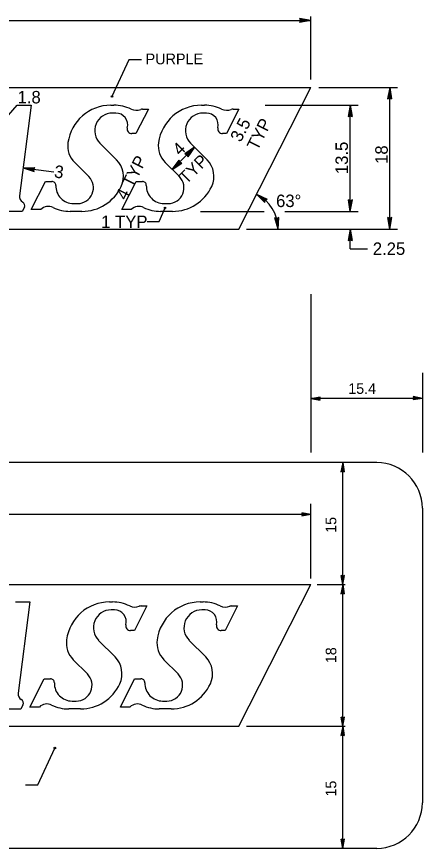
# Model space of a CAD drawing. Extents: x 10268197 to 10269179, y 2141503 to 2142677.
# Drawn here: x 10268707.3 to 10268734, y 2142212.3 to 2142267 of the extents above; entities that cross this region are included whole.
import ezdxf

# ---------------------------------------------------------------- set-up
doc = ezdxf.new("R2010")
doc.units = 0
for name, color, linetype in [('1', 7, 'Continuous'), ('2', 7, 'Continuous'), ('21', 7, 'Continuous'), ('52', 7, 'Continuous'), ('SOILS_SP83_SHP', 7, 'Continuous')]:
    doc.layers.add(name, color=color, linetype=linetype)

msp = doc.modelspace()

# ---------------------------------------------------------------- linework, layer by layer
at = {"layer": '1'}
for p, q in [((10268726.659, 2142262.902), (10268726.659, 2142267.042)), ((10268704.204, 2142266.783), (10268726.659, 2142266.783)), ((10268714.696, 2142264.199), (10268713.581, 2142261.792)), ((10268715.518, 2142264.199), (10268714.696, 2142264.199)), ((10268727.176, 2142262.385), (10268732.351, 2142262.385)), ((10268731.833, 2142253.071), (10268731.833, 2142262.385)), ((10268723.657, 2142261.22), (10268729.764, 2142261.22)), ((10268729.246, 2142254.235), (10268729.246, 2142261.22)), ((10268717.551, 2142256.985), (10268719.015, 2142258.448)), ((10268707.744, 2142257.097), (10268709.761, 2142256.835)), ((10268716.692, 2142253.575), (10268717.072, 2142254.463)), ((10268719.401, 2142254.235), (10268723.596, 2142254.235)), ((10268724.948, 2142254.235), (10268729.764, 2142254.235)), ((10268715.888, 2142253.575), (10268716.692, 2142253.575)), ((10268722.431, 2142253.071), (10268732.351, 2142253.071)), ((10268729.246, 2142251.778), (10268729.246, 2142253.071)), ((10268729.246, 2142251.778), (10268730.371, 2142251.778)), ((10268726.659, 2142248.802), (10268726.659, 2142238.369)), ((10268733.979, 2142243.611), (10268733.979, 2142238.369)), ((10268733.421, 2142241.949), (10268733.373, 2142241.843)), ((10268733.979, 2142241.939), (10268733.373, 2142241.843)), ((10268733.979, 2142241.939), (10268733.377, 2142242.056)), ((10268733.377, 2142242.056), (10268733.421, 2142241.949)), ((10268733.979, 2142241.939), (10268733.399, 2142241.899)), ((10268733.979, 2142241.939), (10268733.401, 2142242)), ((10268728.747, 2142237.716), (10268728.631, 2142237.115)), ((10268728.747, 2142237.716), (10268728.687, 2142237.138)), ((10268728.747, 2142229.69), (10268728.747, 2142237.716)), ((10268728.747, 2142237.716), (10268728.844, 2142237.111)), ((10268728.747, 2142237.716), (10268728.788, 2142237.137)), ((10268728.631, 2142237.115), (10268728.738, 2142237.159)), ((10268728.738, 2142237.159), (10268728.844, 2142237.111)), ((10268726.659, 2142230.104), (10268726.659, 2142234.996)), ((10268726.102, 2142234.302), (10268726.053, 2142234.196)), ((10268726.659, 2142234.292), (10268726.053, 2142234.196)), ((10268726.659, 2142234.292), (10268726.057, 2142234.409)), ((10268726.057, 2142234.409), (10268726.102, 2142234.302)), ((10268726.659, 2142234.292), (10268726.079, 2142234.252)), ((10268726.659, 2142234.292), (10268726.081, 2142234.353)), ((10268728.747, 2142229.69), (10268728.652, 2142230.295)), ((10268728.757, 2142230.247), (10268728.652, 2142230.295)), ((10268728.747, 2142229.69), (10268728.707, 2142230.27)), ((10268728.747, 2142229.69), (10268728.864, 2142230.292)), ((10268728.747, 2142229.69), (10268728.808, 2142230.269)), ((10268728.864, 2142230.292), (10268728.757, 2142230.247)), ((10268727.073, 2142229.69), (10268728.904, 2142229.69)), ((10268728.747, 2142229.69), (10268728.631, 2142229.088)), ((10268728.747, 2142229.69), (10268728.687, 2142229.111)), ((10268728.747, 2142220.374), (10268728.747, 2142229.69)), ((10268728.747, 2142229.69), (10268728.844, 2142229.084)), ((10268728.747, 2142229.69), (10268728.788, 2142229.11)), ((10268728.631, 2142229.088), (10268728.738, 2142229.133)), ((10268728.738, 2142229.133), (10268728.844, 2142229.084)), ((10268728.747, 2142220.374), (10268728.652, 2142220.979)), ((10268728.757, 2142220.931), (10268728.652, 2142220.979)), ((10268728.747, 2142220.374), (10268728.707, 2142220.954)), ((10268728.747, 2142220.374), (10268728.864, 2142220.976)), ((10268728.747, 2142220.374), (10268728.808, 2142220.953)), ((10268728.864, 2142220.976), (10268728.757, 2142220.931)), ((10268722.43, 2142220.374), (10268728.904, 2142220.374)), ((10268728.747, 2142220.374), (10268728.631, 2142219.772)), ((10268728.747, 2142220.374), (10268728.687, 2142219.795)), ((10268728.747, 2142212.347), (10268728.747, 2142220.374)), ((10268728.747, 2142220.374), (10268728.844, 2142219.768)), ((10268728.747, 2142220.374), (10268728.788, 2142219.794)), ((10268728.631, 2142219.772), (10268728.738, 2142219.816)), ((10268728.738, 2142219.816), (10268728.844, 2142219.768)), ((10268708.719, 2142216.536), (10268709.835, 2142218.944)), ((10268707.897, 2142216.536), (10268708.719, 2142216.536)), ((10268728.747, 2142212.347), (10268728.652, 2142212.953)), ((10268728.757, 2142212.905), (10268728.652, 2142212.953)), ((10268728.747, 2142212.347), (10268728.707, 2142212.927)), ((10268728.747, 2142212.347), (10268728.864, 2142212.949)), ((10268728.747, 2142212.347), (10268728.808, 2142212.926)), ((10268728.864, 2142212.949), (10268728.757, 2142212.905))]:
    msp.add_line(p, q, dxfattribs=at)
for centre, radius in [((10268713.581, 2142261.791), 0.0517), ((10268717.072, 2142254.462), 0.0517), ((10268709.835, 2142218.944), 0.0518)]:
    msp.add_circle(centre, radius, dxfattribs=at)
msp.add_arc((10268721.913, 2142253.07), 2.587, 0, 63.0012, dxfattribs=at)
at = {"layer": '2'}
for p, q in [((10268733.979, 2142241.939), (10268726.659, 2142241.939)), ((10268730.979, 2142237.716), (10268669.979, 2142237.716)), ((10268733.979, 2142234.716), (10268733.979, 2142215.347)), ((10268726.659, 2142234.292), (10268674.298, 2142234.292)), ((10268697.136, 2142229.69), (10268726.659, 2142229.69)), ((10268721.913, 2142220.374), (10268726.659, 2142229.69)), ((10268707.256, 2142228.551), (10268708.188, 2142228.551)), ((10268708.188, 2142228.551), (10268707.413, 2142222.551)), ((10268713.423, 2142228.551), (10268713.619, 2142228.551)), ((10268713.751, 2142228.03), (10268713.529, 2142228.03)), ((10268715.885, 2142228.291), (10268715.063, 2142226.665)), ((10268715.497, 2142228.291), (10268715.885, 2142228.291)), ((10268719.375, 2142228.551), (10268719.571, 2142228.551)), ((10268719.702, 2142228.03), (10268719.48, 2142228.03)), ((10268721.837, 2142228.291), (10268721.014, 2142226.665)), ((10268721.449, 2142228.291), (10268721.837, 2142228.291)), ((10268715.063, 2142226.665), (10268714.804, 2142226.665)), ((10268721.014, 2142226.665), (10268720.756, 2142226.665)), ((10268712.705, 2142226.027), (10268713.79, 2142224.935)), ((10268718.657, 2142226.027), (10268719.742, 2142224.935)), ((10268711.974, 2142223.814), (10268711.043, 2142224.752)), ((10268717.926, 2142223.814), (10268716.994, 2142224.752)), ((10268708.185, 2142221.643), (10268709.124, 2142223.502)), ((10268709.124, 2142223.502), (10268709.54, 2142223.502)), ((10268714.136, 2142221.643), (10268715.076, 2142223.502)), ((10268715.076, 2142223.502), (10268715.492, 2142223.502)), ((10268710.963, 2142222.034), (10268711.243, 2142222.034)), ((10268716.915, 2142222.034), (10268717.194, 2142222.034)), ((10268707.601, 2142221.512), (10268705.014, 2142221.512)), ((10268707.737, 2142221.781), (10268707.601, 2142221.512)), ((10268708.813, 2142221.643), (10268708.185, 2142221.643)), ((10268711.52, 2142221.513), (10268710.742, 2142221.513)), ((10268714.765, 2142221.643), (10268714.136, 2142221.643)), ((10268717.472, 2142221.513), (10268716.693, 2142221.513)), ((10268696.271, 2142220.374), (10268721.913, 2142220.374)), ((10268730.979, 2142212.347), (10268669.979, 2142212.347))]:
    msp.add_line(p, q, dxfattribs=at)
for centre, start, end in [((10268730.979, 2142234.716), 0, 90), ((10268730.979, 2142215.347), 270, 0)]:
    msp.add_arc(centre, 3, start, end, dxfattribs=at)
for centre, major_axis, start_param, end_param in [((10268713.423, 2142225.684), (0, 2.868), 0, 1.436562), ((10268713.529, 2142226.857), (0, -1.173), 3.141593, 5.497787), ((10268713.619, 2142225.945), (0, 2.607), 5.830963, 6.283185), ((10268713.751, 2142227.248), (0, -0.782), 1.321066, 3.141593), ((10268715.089, 2142228.993), (0, 0.782), 2.68937, 3.526171), ((10268715.497, 2142227.978), (0, 0.313), 0, 0.384579), ((10268719.375, 2142225.684), (0, 2.868), 0, 1.436562), ((10268719.48, 2142226.857), (0, -1.173), 3.141593, 5.497787), ((10268719.571, 2142225.945), (0, 2.607), 5.830963, 6.283185), ((10268719.702, 2142227.248), (0, -0.782), 1.321066, 3.141593), ((10268721.041, 2142228.993), (0, 0.782), 2.68937, 3.526171), ((10268721.449, 2142227.978), (0, 0.313), 0, 0.384579), ((10268714.804, 2142226.978), (0, -0.313), 4.462658, 6.283185), ((10268720.756, 2142226.978), (0, -0.313), 4.462658, 6.283185), ((10268712.141, 2142225.858), (0, 1.564), 1.436562, 2.356194), ((10268718.092, 2142225.858), (0, 1.564), 1.436562, 2.356194), ((10268712.692, 2142223.829), (0, -1.564), 1.133591, 2.356194), ((10268718.644, 2142223.829), (0, -1.564), 1.133591, 2.356194), ((10268711.242, 2142223.077), (0, -1.043), 0, 2.356194), ((10268717.194, 2142223.077), (0, -1.043), 0, 2.356194), ((10268709.54, 2142223.241), (0, 0.261), 4.689114, 6.283185), ((10268710.963, 2142223.207), (0, 1.173), 1.547521, 3.141593), ((10268711.52, 2142224.381), (0, -2.868), 0, 1.133591), ((10268715.492, 2142223.241), (0, 0.261), 4.689114, 6.283185), ((10268716.915, 2142223.207), (0, 1.173), 1.547521, 3.141593), ((10268717.472, 2142224.381), (0, -2.868), 0, 1.133591), ((10268707.824, 2142222.498), (0, 0.417), 1.441439, 2.650585), ((10268707.507, 2142221.9), (0, 0.261), 4.240773, 5.792177), ((10268709.309, 2142221.111), (0, -0.73), 2.69443, 3.895387), ((10268710.741, 2142224.12), (0, -2.607), 5.836023, 6.283185), ((10268715.261, 2142221.111), (0, -0.73), 2.69443, 3.895387), ((10268716.693, 2142224.12), (0, -2.607), 5.836023, 6.283185)]:
    msp.add_ellipse(centre, major_axis=major_axis, ratio=0.992614, start_param=start_param, end_param=end_param, dxfattribs=at)
at = {"layer": '21'}
for p, q in [((10268726.659, 2142241.939), (10268727.264, 2142242.035)), ((10268726.659, 2142241.939), (10268727.239, 2142241.98)), ((10268726.659, 2142241.939), (10268727.261, 2142241.822)), ((10268726.659, 2142241.939), (10268727.237, 2142241.879)), ((10268727.216, 2142241.93), (10268727.264, 2142242.035)), ((10268727.261, 2142241.822), (10268727.216, 2142241.93))]:
    msp.add_line(p, q, dxfattribs=at)
at = {"layer": '52'}
for p, q in [((10268726.659, 2142266.783), (10268725.907, 2142266.929)), ((10268725.907, 2142266.929), (10268725.962, 2142266.795)), ((10268726.659, 2142266.783), (10268725.936, 2142266.859)), ((10268725.962, 2142266.795), (10268725.903, 2142266.663)), ((10268726.659, 2142266.783), (10268725.903, 2142266.663)), ((10268726.659, 2142266.783), (10268725.935, 2142266.732)), ((10268731.833, 2142262.385), (10268731.687, 2142261.633)), ((10268731.833, 2142262.385), (10268731.758, 2142261.662)), ((10268731.833, 2142262.385), (10268731.953, 2142261.628)), ((10268731.833, 2142262.385), (10268731.884, 2142261.66)), ((10268731.687, 2142261.633), (10268731.821, 2142261.688)), ((10268731.821, 2142261.688), (10268731.953, 2142261.628)), ((10268729.246, 2142261.22), (10268729.1, 2142260.469)), ((10268729.246, 2142261.22), (10268729.171, 2142260.498)), ((10268729.246, 2142261.22), (10268729.366, 2142260.464)), ((10268729.246, 2142261.22), (10268729.297, 2142260.496)), ((10268729.1, 2142260.469), (10268729.234, 2142260.525)), ((10268729.234, 2142260.525), (10268729.366, 2142260.464)), ((10268719.015, 2142258.448), (10268718.38, 2142258.02)), ((10268719.015, 2142258.448), (10268718.45, 2142257.991)), ((10268719.015, 2142258.448), (10268718.538, 2142257.9)), ((10268719.015, 2142258.448), (10268718.565, 2142257.828)), ((10268717.551, 2142256.985), (10268718.001, 2142257.604)), ((10268718.052, 2142257.469), (10268718.001, 2142257.604)), ((10268718.38, 2142258.02), (10268718.514, 2142257.964)), ((10268718.514, 2142257.964), (10268718.565, 2142257.828)), ((10268707.744, 2142257.097), (10268708.51, 2142257.119)), ((10268707.744, 2142257.097), (10268708.47, 2142256.855)), ((10268707.744, 2142257.097), (10268708.451, 2142256.929)), ((10268707.744, 2142257.097), (10268708.469, 2142257.054)), ((10268708.433, 2142256.996), (10268708.51, 2142257.119)), ((10268717.551, 2142256.985), (10268718.028, 2142257.532)), ((10268717.551, 2142256.985), (10268718.116, 2142257.442)), ((10268717.551, 2142256.985), (10268718.186, 2142257.413)), ((10268718.186, 2142257.413), (10268718.052, 2142257.469)), ((10268708.47, 2142256.855), (10268708.433, 2142256.996)), ((10268723.088, 2142255.376), (10268723.777, 2142255.04)), ((10268723.088, 2142255.376), (10268723.62, 2142254.825)), ((10268723.088, 2142255.376), (10268723.637, 2142254.9)), ((10268723.088, 2142255.376), (10268723.711, 2142255.002)), ((10268723.62, 2142254.825), (10268723.651, 2142254.968)), ((10268723.651, 2142254.968), (10268723.777, 2142255.04)), ((10268729.246, 2142254.235), (10268729.126, 2142254.991)), ((10268729.258, 2142254.931), (10268729.126, 2142254.991)), ((10268729.246, 2142254.235), (10268729.195, 2142254.959)), ((10268729.246, 2142254.235), (10268729.392, 2142254.987)), ((10268729.246, 2142254.235), (10268729.321, 2142254.959)), ((10268729.392, 2142254.987), (10268729.258, 2142254.931)), ((10268724.5, 2142253.071), (10268724.276, 2142253.803)), ((10268724.416, 2142253.763), (10268724.276, 2142253.803)), ((10268724.5, 2142253.071), (10268724.35, 2142253.782)), ((10268724.54, 2142253.836), (10268724.416, 2142253.763)), ((10268724.5, 2142253.071), (10268724.476, 2142253.798)), ((10268724.5, 2142253.071), (10268724.54, 2142253.836)), ((10268731.833, 2142253.071), (10268731.713, 2142253.828)), ((10268731.845, 2142253.768), (10268731.713, 2142253.828)), ((10268731.833, 2142253.071), (10268731.783, 2142253.795)), ((10268731.833, 2142253.071), (10268731.979, 2142253.823)), ((10268731.833, 2142253.071), (10268731.908, 2142253.794)), ((10268731.979, 2142253.823), (10268731.845, 2142253.768)), ((10268729.246, 2142253.071), (10268729.1, 2142252.319)), ((10268729.246, 2142253.071), (10268729.171, 2142252.348)), ((10268729.246, 2142253.071), (10268729.366, 2142252.315)), ((10268729.246, 2142253.071), (10268729.297, 2142252.347)), ((10268729.1, 2142252.319), (10268729.234, 2142252.375)), ((10268729.234, 2142252.375), (10268729.366, 2142252.315))]:
    msp.add_line(p, q, dxfattribs=at)
at = {"layer": 'SOILS_SP83_SHP'}
for p, q in [((10268697.142, 2142262.385), (10268726.659, 2142262.385)), ((10268721.913, 2142253.071), (10268726.659, 2142262.385)), ((10268702.066, 2142255.144), (10268707.349, 2142261.22)), ((10268707.349, 2142261.22), (10268708.281, 2142261.22)), ((10268708.281, 2142261.22), (10268707.506, 2142255.266)), ((10268713.514, 2142261.22), (10268713.711, 2142261.22)), ((10268715.976, 2142260.961), (10268715.153, 2142259.348)), ((10268715.588, 2142260.961), (10268715.976, 2142260.961)), ((10268719.465, 2142261.22), (10268719.661, 2142261.22)), ((10268721.926, 2142260.961), (10268721.104, 2142259.348)), ((10268721.538, 2142260.961), (10268721.926, 2142260.961)), ((10268713.842, 2142260.703), (10268713.62, 2142260.703)), ((10268719.793, 2142260.703), (10268719.571, 2142260.703)), ((10268715.153, 2142259.348), (10268714.895, 2142259.348)), ((10268721.104, 2142259.348), (10268720.845, 2142259.348)), ((10268712.797, 2142258.716), (10268713.881, 2142257.631)), ((10268718.747, 2142258.716), (10268719.832, 2142257.631)), ((10268712.066, 2142256.519), (10268711.135, 2142257.45)), ((10268718.016, 2142256.519), (10268717.086, 2142257.45)), ((10268708.277, 2142254.365), (10268709.216, 2142256.209)), ((10268709.216, 2142256.209), (10268709.632, 2142256.209)), ((10268714.227, 2142254.365), (10268715.167, 2142256.209)), ((10268715.167, 2142256.209), (10268715.583, 2142256.209)), ((10268707.83, 2142254.502), (10268707.694, 2142254.235)), ((10268708.906, 2142254.365), (10268708.277, 2142254.365)), ((10268711.054, 2142254.752), (10268711.334, 2142254.752)), ((10268714.856, 2142254.365), (10268714.227, 2142254.365)), ((10268717.005, 2142254.752), (10268717.284, 2142254.752)), ((10268707.694, 2142254.235), (10268705.107, 2142254.235)), ((10268711.612, 2142254.235), (10268710.834, 2142254.235)), ((10268717.563, 2142254.235), (10268716.784, 2142254.235)), ((10268696.456, 2142253.071), (10268721.913, 2142253.071))]:
    msp.add_line(p, q, dxfattribs=at)
for centre, radius, start, end in [((10268713.514, 2142258.374), 2.846, 90, 172.3089), ((10268713.71, 2142258.633), 2.587, 64.0896, 90), ((10268715.18, 2142261.658), 0.776, 244.0896, 292.0347), ((10268715.588, 2142260.651), 0.31, 90, 112.0347), ((10268719.465, 2142258.374), 2.846, 90, 172.3089), ((10268719.661, 2142258.633), 2.587, 64.0896, 90), ((10268721.131, 2142261.658), 0.776, 244.0896, 292.0347), ((10268721.538, 2142260.651), 0.31, 90, 112.0347), ((10268713.62, 2142259.538), 1.164, 90, 225), ((10268713.842, 2142259.926), 0.776, 345.6915, 90), ((10268719.57, 2142259.538), 1.164, 90, 225), ((10268719.792, 2142259.926), 0.776, 345.6915, 90), ((10268714.895, 2142259.658), 0.31, 165.6915, 270), ((10268720.845, 2142259.658), 0.31, 165.6915, 270), ((10268712.232, 2142258.547), 1.552, 172.3089, 225), ((10268718.183, 2142258.547), 1.552, 172.3089, 225), ((10268712.784, 2142256.533), 1.552, 334.95, 45), ((10268718.734, 2142256.533), 1.552, 334.95, 45), ((10268711.334, 2142255.787), 1.035, 270, 45), ((10268717.284, 2142255.787), 1.035, 270, 45), ((10268709.632, 2142255.949), 0.259, 358.6664, 90), ((10268711.055, 2142255.916), 1.164, 178.6665, 270), ((10268715.583, 2142255.949), 0.259, 358.6664, 90), ((10268717.005, 2142255.916), 1.164, 178.6665, 270), ((10268711.612, 2142257.08), 2.846, 270, 334.95), ((10268717.562, 2142257.08), 2.846, 270, 334.95), ((10268707.916, 2142255.212), 0.414, 172.5884, 241.8673), ((10268707.599, 2142254.619), 0.259, 332.9784, 61.8673), ((10268709.401, 2142253.836), 0.724, 64.3795, 133.1892), ((10268710.833, 2142256.822), 2.587, 244.3795, 270), ((10268715.352, 2142253.836), 0.724, 64.3795, 133.1892), ((10268716.784, 2142256.822), 2.587, 244.3795, 270)]:
    msp.add_arc(centre, radius, start, end, dxfattribs=at)

# ---------------------------------------------------------------- texts
at = {"layer": '1'}
for s, height, p in [('PURPLE', 0.706, (10268715.798, 2142263.905)), ('1.8', 0.8187, (10268707.383, 2142261.337)), ('63°', 0.8187, (10268724.368, 2142254.52)), ('1 TYP', 0.8187, (10268712.877, 2142253.142)), ('2.25', 0.8187, (10268730.723, 2142251.372)), ('15.4', 0.7, (10268729.114, 2142242.234))]:
    msp.add_text(s, height=height, dxfattribs=at).set_placement(p)
for s, height, rotation, p in [('3.5', 0.8187, 63, (10268722.044, 2142258.737)), ('TYP', 0.8187, 63, (10268723.138, 2142258.18)), ('4', 0.819, 45, (10268718.06, 2142257.856)), ('13.5', 0.8187, 90, (10268729.09, 2142256.686)), ('18', 0.8187, 90, (10268731.703, 2142257.359)), ('4 TYP', 0.8187, 62.9993, (10268714.522, 2142254.917)), ('TYP', 0.8187, 45, (10268718.469, 2142255.971)), ('3', 0.819, 352.5994, (10268709.753, 2142256.469)), ('15', 0.7, 90, (10268728.326, 2142233.098)), ('18', 0.7, 90, (10268728.326, 2142224.528)), ('15', 0.7, 90, (10268728.326, 2142215.756))]:
    msp.add_text(s, height=height, rotation=rotation, dxfattribs=at).set_placement(p)

doc.saveas('drawing.dxf')
